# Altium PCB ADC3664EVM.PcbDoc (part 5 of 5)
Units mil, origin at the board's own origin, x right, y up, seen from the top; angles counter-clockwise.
Board outline 3900 x 2716.54 mil, 10 copper layers (Top Layer, L2 GND, L3 PWR, L4 GND, L5 SIG, L6 GND, L7 GND, L8 PWR, L9 GND, Bottom Layer), stack 61.2 mil thick; 332 components, 223 nets, 1425 pads, 969 vias.
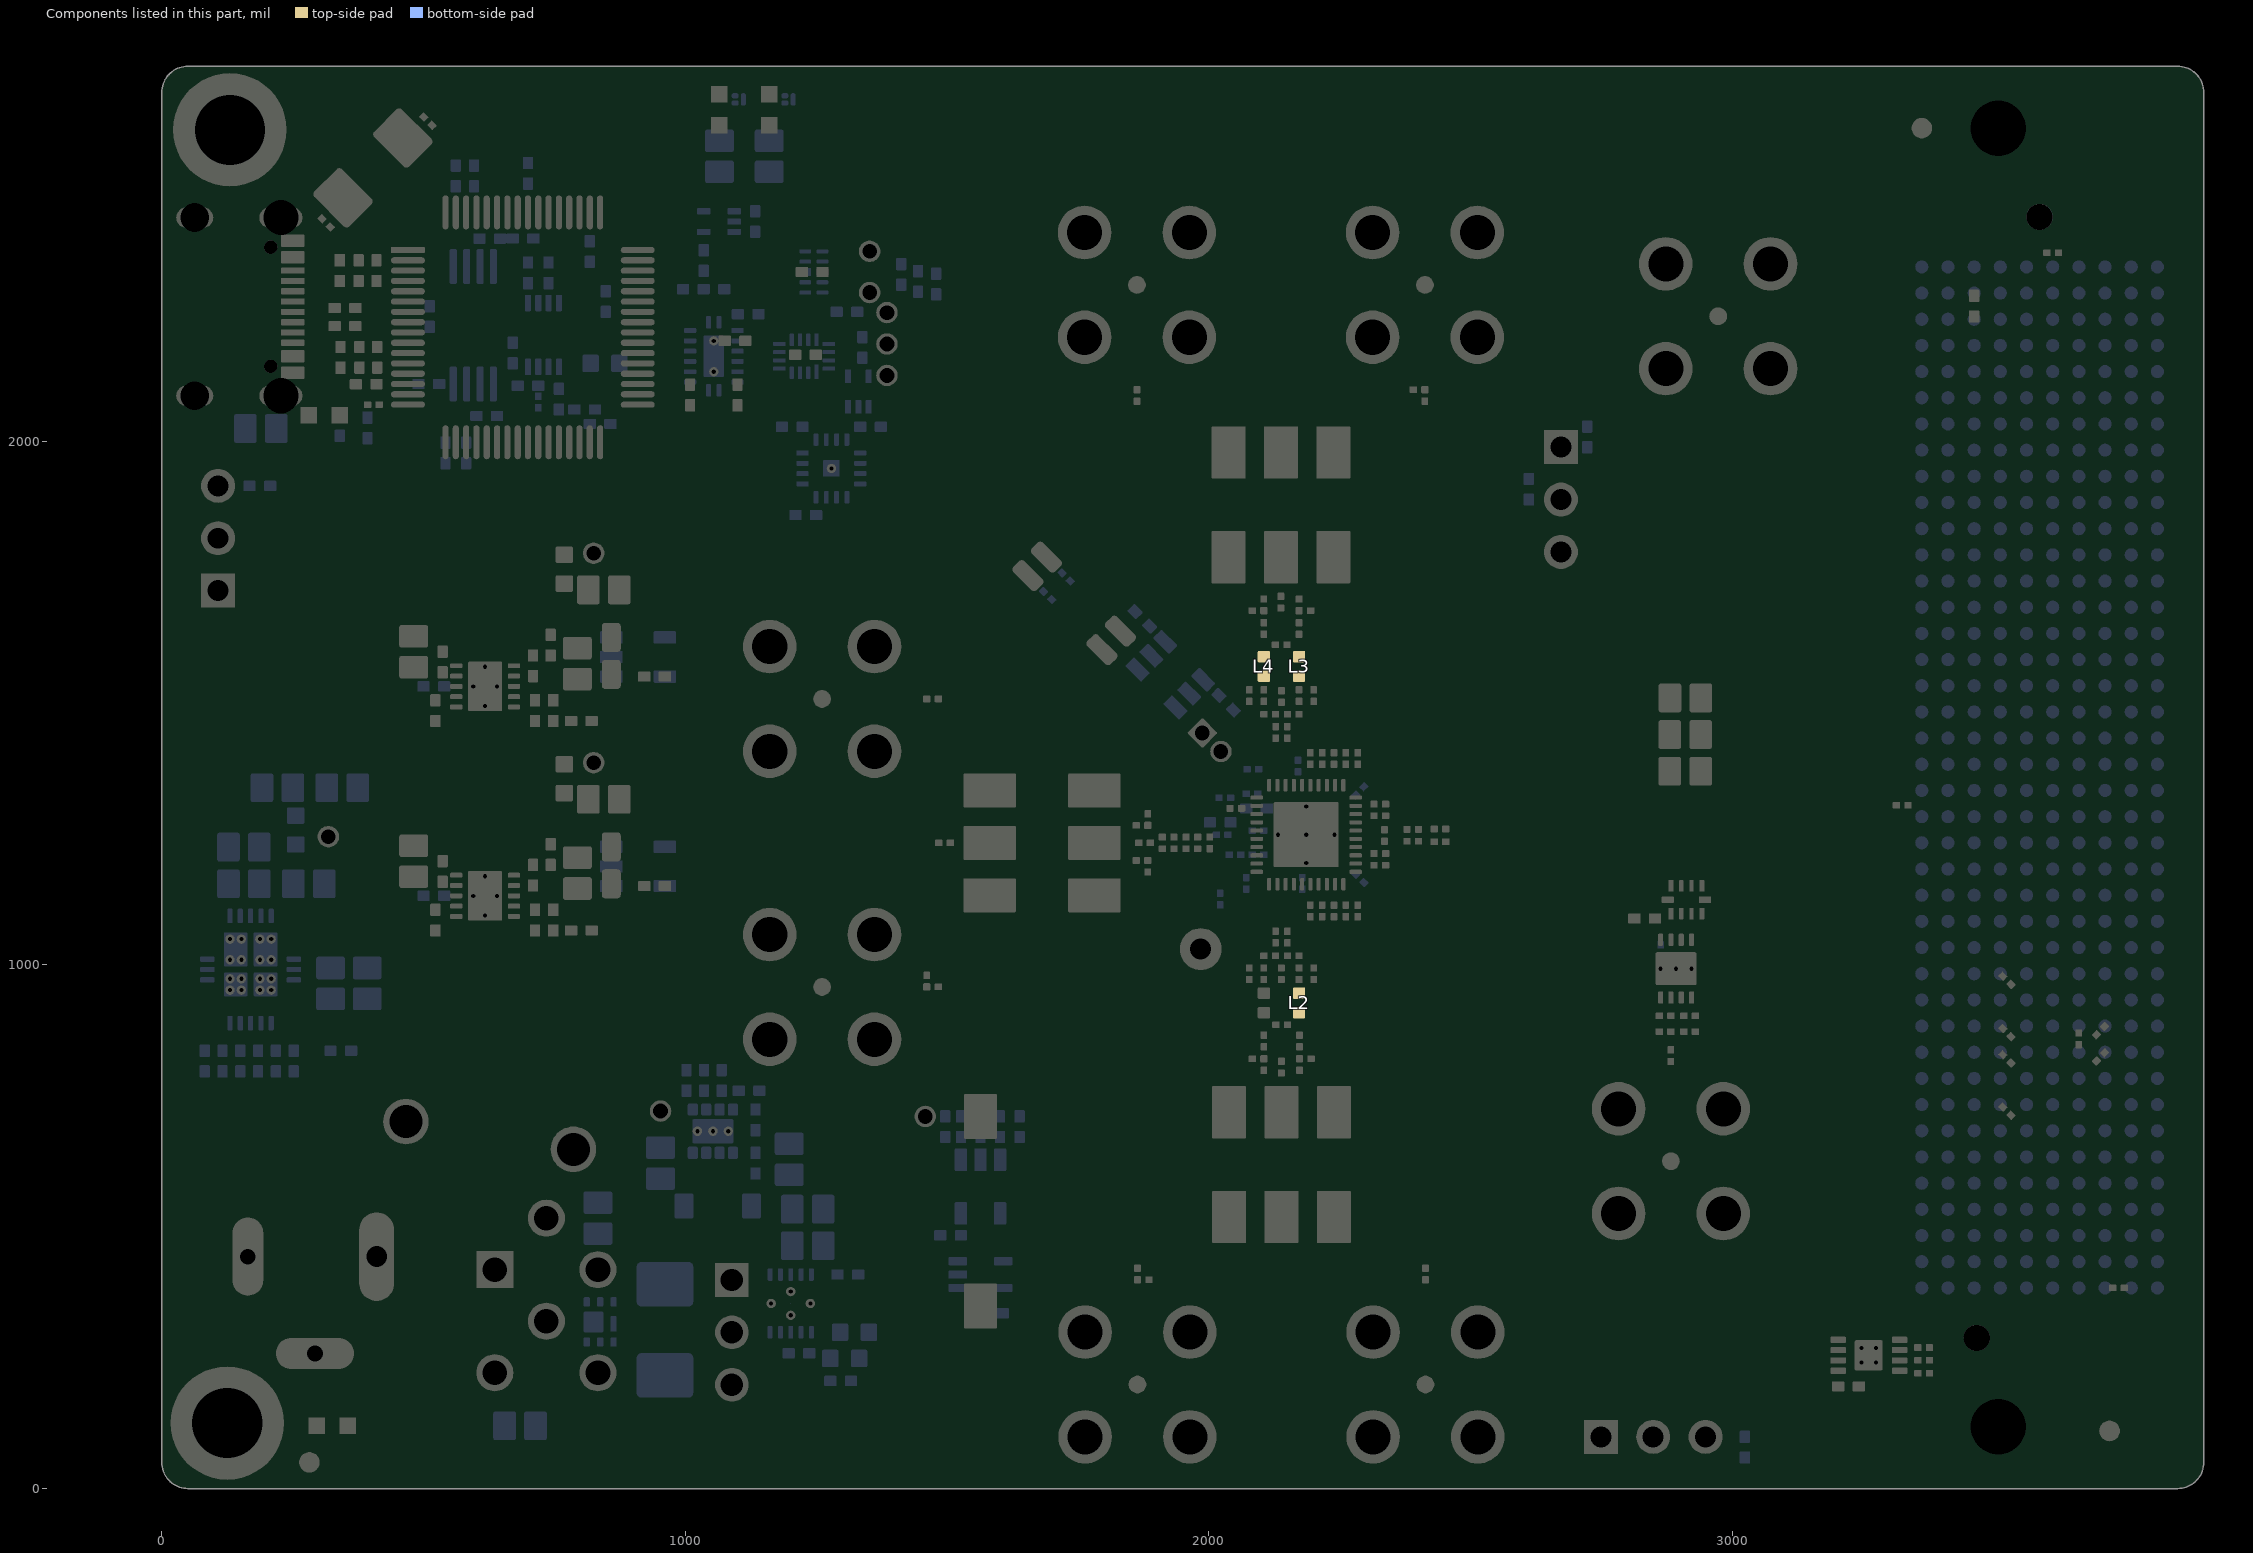
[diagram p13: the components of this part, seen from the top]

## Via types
v1: diameter 18, hole 8, Top Layer to Bottom Layer, tented both sides, 952 vias
v2: diameter 40, hole 20, Top Layer to Bottom Layer, tented both sides, 14 vias
v3: diameter 18, hole 8, Top Layer to Bottom Layer, tented bottom, 3 vias

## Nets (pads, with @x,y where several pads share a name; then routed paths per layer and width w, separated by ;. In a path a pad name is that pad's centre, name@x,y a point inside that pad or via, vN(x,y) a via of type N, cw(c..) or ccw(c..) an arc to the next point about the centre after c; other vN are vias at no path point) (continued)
pads on no net: FID1.1 FID2.1 FID3.1 H1. H3. J1. J1.A2 J1.A3 J1.A6 J1.A7 J1.A10 J1.A11 J1.A14 J1.A15 J1.A18 J1.A19 J1.A22 J1.A23 J1.A26 J1.A27 J1.A30 J1.A31 J1.A34 J1.A35 J1.A38 J1.A39 J1.B1 J1.B4 J1.B5 J1.B8 J1.B9 J1.B12 J1.B13 J1.B16 J1.B17 J1.B20 J1.B21 J1.B24 J1.B25 J1.B28 J1.B29 J1.B32 J1.B33 J1.B36 J1.B37 J1.C2 J1.C3 J1.C6 J1.C7 J1.C10 J1.C11 J1.C14 J1.C15 J1.C18 J1.C19 J1.C22 J1.C23 J1.C26 J1.C27 J1.C39 J1.D4 J1.D5 J1.D14 J1.D15 J1.D17 J1.D18 J1.D20 J1.D21 J1.D23 J1.D24 J1.D26 J1.D27 J1.D29 J1.D33 J1.D34 J1.D36 J1.D38 J1.D40 J1.E2 J1.E3 J1.E6 J1.E7 J1.E9 J1.E10 J1.E12 J1.E13 J1.E15 J1.E16 J1.E18 J1.E19 J1.E21 J1.E22 J1.E24 J1.E25 J1.E27 J1.E28 J1.E30 J1.E31 J1.E33 J1.E34 J1.E36 J1.E37 J1.F4 J1.F5 J1.F7 J1.F8 J1.F10 J1.F11 J1.F13 J1.F14 J1.F16 J1.F17 J1.F19 J1.F20 J1.F22 J1.F23 J1.F25 J1.F26 J1.F28 J1.F29 J1.F31 J1.F32 J1.F34 J1.F35 J1.F37 J1.F38 J1.G2 J1.G3 J1.G12 J1.G13 J1.G15 J1.G16 J1.G18 J1.G19 J1.G22 J1.G24 J1.G25 J1.G27 J1.G34 J1.G36 J1.G37 J1.H1 J1.H10 J1.H11 J1.H16 J1.H17 J1.H19 J1.H20 J1.H22 J1.H23 J1.H25 J1.H26 J1.H28 J1.H29 J1.H31 J1.H32 J1.H34 J1.H35 J1.H37 J1.H38 J1.J2 J1.J3 J1.J6 J1.J7 J1.J9 J1.J10 J1.J12 J1.J13 J1.J15 J1.J16 J1.J18 J1.J19 J1.J21 J1.J22 J1.J24 J1.J25 J1.J27 J1.J28 J1.J30 J1.J31 J1.J33 J1.J34 J1.J36 J1.J37 J1.J39 J1.K1 J1.K4 J1.K5 J1.K7 J1.K8 J1.K10 J1.K11 J1.K13 J1.K14 J1.K16 J1.K17 J1.K19 J1.K20 J1.K22 J1.K23 J1.K25 J1.K27 J1.K28 J1.K29 J1.K31 J1.K32 J1.K34 J1.K35 J1.K37 J1.K38 J1.K40 J3. J3.A5 J3.A8 J3.B5 J3.B8 Q1.0 Q2.1@1095,2645.24 Q2.2@1095,2660.98 Q3.1@1190,2645.24 Q3.2@1190,2660.98 R100.1 R100.2 R101.1 R101.2 R102.1 R102.2 SH-J1.0 U2.9 U3.0 U4.4 U11.21 U11.22 U11.23 U11.24 U11.29 U11.30 U11.32 U11.33 U11.34 U11.36 U11.38 U11.39 U11.40 U11.41 U11.43 U11.44 U11.45 U11.46 U11.48 U11.52 U11.53 U11.54 U11.55 U11.57 U11.58 U11.59 U11.60 U12.6 U12.7 U13.3@1228.98,2323.6 U13.8@1261.85,2323.6 U15.10 U15.11 U15.12 U18.5 U21.5

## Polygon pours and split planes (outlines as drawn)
GND on L8 PWR "L2 GND-GND" (solid, remove dead copper, pour order 102): 3900,-3.61 3900,2716.53 0,2716.54 0,-3.61
3p3V_Utility on L8 PWR "L8 PWR-3p3V_Utility" (solid, remove dead copper, pour order 97): 155,760 265,760 265,1015 595,1015 595,605.64 1290,605.64 1290,416.86 786.24,416.86 786.24,-5 3320,-5 3320,100 1035,100 1035,248.29 3017.11,248.29 3017.11,2015 1389.6,2015 1389.6,2545 1390,2545 1390,2716.54 1265,2716.54 1265,2622.3 155,2622.3
2p3V on L8 PWR "vcm" (solid, remove dead copper, pour order 48): 170,1140 560,1140 560,1422.72 496.81,1422.72 496.81,1505.28 570,1505.28 570,1705 170,1705
12V on L8 PWR "L8 PWR-12V" (solid, remove dead copper, pour order 34): 0,-5 275,-5 275.6,-5 790,-5 790,416.86 1290,416.86 1290,605.64 595,605.64 595,1015 275.6,1015 275.6,745 140,745 140,2635 1257.39,2635 1257.39,2715 0,2715
1p8V_LVLSHIFT on L8 PWR "1" (solid, pour order 24): 1580,1639.12 1755,1639.12 1755,2415 1405,2415 1405,1640 1580,1640
12V_FMC on L8 PWR "gnd" (solid, remove dead copper, pour order 69): 3635,660 3791.17,660 3791.17,105 997.3,105 997.3,253.29 2785,253.29 3635,253.29
VCORE on L8 PWR "L10 PWR-VCORE" (solid, remove dead copper, pour order 55): 948.98,2112.51 948.98,2470 637.92,2470 637.92,2479.2 470,2479.2 470,2126.19 637.92,2126.19 637.92,2410 876.5,2410 876.5,2192.06 845,2192.06 845,2112.51
GND on L5 SIG "L2 GND-GND" (solid, remove dead copper, pour order 101): 3900,-3.61 3900,2716.53 0,2716.54 0,-3.61
GND on L5 SIG "gnd" (solid, remove dead copper, pour order 54): 1895,1450 1895,1235 2130,1235 2130,1450
VREF on L5 SIG "gnd" (solid, remove dead copper, pour order 39): 1978.88,1424.46 1978.88,1285 2085.6,1285 2085.6,1424.46
VCM on L5 SIG "L5 SIG-VCM" (solid, remove dead copper, pour order 42): 1885,945 2468.65,945 2468.65,1540 2080,1540 2080,1480.69 2130,1480.69 2130,1225 1885,1225
EXTGND on L5 SIG "NONET_L-01_P-001" (solid, remove dead copper, pour order 38): 688.31,766.34 0,766.34 0,50 ccw(c50,50) 50,0 688.31,0
GND on L2 GND "L2 GND-GND" (solid, remove dead copper, pour order 71): 3900,-3.61 3900,2716.53 0,2716.54 0,-3.61
EXTGND on L2 GND "NONET_L-01_P-001" (solid, remove dead copper, pour order 7): 688.31,766.34 0,766.34 0,50 ccw(c50,50) 50,0 688.31,0
GND on L6 GND "L2 GND-GND" (solid, remove dead copper, pour order 76): 3900,-3.61 3900,2716.53 556.54,2716.54 ccw(c556.53,2660.06) 536.65,2712.92 56.54,2712.92 ccw(c56.53,2656.39) 0,2656.39 0,46.39 ccw(c50,46.39) 50,-3.61
EXTGND on L6 GND "NONET_L-01_P-001" (solid, remove dead copper, pour order 57): 688.31,766.34 0,766.34 0,50 ccw(c50,50) 50,0 688.31,0
GND on Top Layer "L2 GND-GND" (solid, remove dead copper, pour order 99): 3900,-3.61 3900,2716.53 0,2716.54 0,-3.61
EXTGND on Top Layer "NONET_L-01_P-001" (solid, remove dead copper, pour order 58): 688.31,766.34 0,766.34 0,50 ccw(c50,50) 50,0 688.31,0
GND on L4 GND "L2 GND-GND" (solid, remove dead copper, pour order 74): 3900,-3.61 3900,2716.53 556.54,2716.54 ccw(c556.53,2660.06) 536.65,2712.92 56.54,2712.92 ccw(c56.53,2656.39) 0,2656.39 0,46.39 ccw(c50,46.39) 50,-3.61
EXTGND on L4 GND "NONET_L-01_P-001" (solid, remove dead copper, pour order 59): 688.31,766.34 0,766.34 0,50 ccw(c50,50) 50,0 688.31,0
GND on L7 GND "L2 GND-GND" (solid, remove dead copper, pour order 77): 3900,-3.61 3900,2716.53 556.54,2716.54 ccw(c556.53,2660.06) 536.65,2712.92 56.54,2712.92 ccw(c56.53,2656.39) 0,2656.39 0,46.39 ccw(c50,46.39) 50,-3.61
EXTGND on L7 GND "NONET_L-01_P-001" (solid, remove dead copper, pour order 60): 688.31,766.34 0,766.34 0,50 ccw(c50,50) 50,0 688.31,0
GND on L9 GND "L2 GND-GND" (solid, remove dead copper, pour order 78): 3900,-3.61 3900,2716.53 556.54,2716.54 ccw(c556.53,2660.06) 536.65,2712.92 56.54,2712.92 ccw(c56.53,2656.39) 0,2656.39 0,46.39 ccw(c50,46.39) 50,-3.61
EXTGND on L9 GND "NONET_L-01_P-001" (solid, remove dead copper, pour order 61): 688.31,766.34 0,766.34 0,50 ccw(c50,50) 50,0 688.31,0
GND on L3 PWR "L2 GND-GND" (solid, remove dead copper, pour order 96): 3900,-3.61 3900,2716.53 556.54,2716.54 ccw(c556.53,2660.06) 536.65,2712.92 56.54,2712.92 ccw(c56.53,2656.39) 0,2656.39 0,46.39 ccw(c50,46.39) 50,-3.61
1p8V_LVLSHIFT on L3 PWR "L3 PWR-1p8V_LVLSHIFT" (solid, pour order 90): 2636.58,697.88 3106.62,697.88 3106.62,2712.92 0,2712.92 0,887.5 1224.31,887.5 1224.31,0 1659.39,0 1659.39,1188.15 1366.99,1188.15 709.12,1191.1 269.17,1191.1 269.17,2033.32 2636.58,2033.32
1p8V_AVDD on L3 PWR "L3 PWR-1p8V_AVDD" (solid, remove dead copper, pour order 92): 2018.18,936.33 2018.64,879.73 2333.72,879.73 2333.72,936.33 2198.25,936.33 2198.25,1785 385,1785 385,1435 2018.64,1435 2018.64,936.33
3p3V_AUX on L3 PWR "vcm" (solid, remove dead copper, pour order 93): 3270,340 3270,0 3900,0 3900,820 3575,820 3575,340
3p3V_EEPROM on L3 PWR "vcm" (solid, remove dead copper, pour order 94): 3270,340 2875,340 2875,0 3270,0 3270,100
1p8V_IOVDD on L3 PWR "L3_PWR_1P8V_IOVDD_P095" (solid, remove dead copper, pour order 95): 385,1205.06 1741.07,1205.06 1741.07,376.16 2621.28,376.16 2621.28,1419.71 2263.63,1419.71 2263.63,819.66 1994.38,819.66 1994.38,1381.33 385,1381.33
EXTGND on L3 PWR "NONET_L-01_P-001" (solid, remove dead copper, pour order 91): 688.31,766.34 0,766.34 0,50 ccw(c50,50) 50,0 688.31,0
GND on Bottom Layer "L2 GND-GND" (solid, remove dead copper, pour order 103): 3900,-3.61 3900,2716.53 0,2716.54 0,-3.61

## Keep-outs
Keep-Out Layer:
  text ".Layer_Name" at 577,-858.49 h60

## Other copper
Top Layer:
  drawing of 99 lines, arcs and shapes, not listed
  text ".Layer_Name" at 577,-858.49 h60
L2 GND:
  pour cut-out: 2907.99,625.2 ccw(c2882.27,625.27) 2900.45,643.45 ccw(c2882.93,625.93) 2882.93,650.72 2881.55,650.72 ccw(c2881.55,625.98) 2864.06,643.47 2863.35,642.76 ccw(c2880.85,625.27) 2856.11,625.27 2856.11,624.57 ccw(c2881.56,624.57) 2863.56,606.57 2863.7,606.43 ccw(c2882.05,624.77) 2882.05,598.83 ccw(c2882.05,624.75) 2900.38,606.42 2900.75,606.79 ccw(c2883.27,624.27) 2907.99,624.27
  pour cut-out: 2998.18,2238.8 ccw(c2972.46,2238.88) 2990.65,2257.06 ccw(c2973.12,2239.54) 2973.12,2264.32 2971.75,2264.32 ccw(c2971.75,2239.59) 2954.26,2257.08 2953.55,2256.37 ccw(c2971.04,2238.88) 2946.3,2238.88 2946.3,2238.17 ccw(c2971.76,2238.17) 2953.76,2220.17 2953.9,2220.03 ccw(c2972.24,2238.38) 2972.24,2212.44 ccw(c2972.24,2238.36) 2990.58,2220.03 2990.94,2220.4 ccw(c2973.47,2237.87) 2998.18,2237.87
  pour cut-out: 2438.18,2298.8 ccw(c2412.46,2298.88) 2430.65,2317.06 ccw(c2413.12,2299.54) 2413.12,2324.32 2411.75,2324.32 ccw(c2411.75,2299.59) 2394.26,2317.08 2393.55,2316.37 ccw(c2411.04,2298.88) 2386.3,2298.88 2386.3,2298.17 ccw(c2411.76,2298.17) 2393.76,2280.17 2393.9,2280.03 ccw(c2412.24,2298.38) 2412.24,2272.44 ccw(c2412.24,2298.36) 2430.58,2280.03 2430.94,2280.4 ccw(c2413.47,2297.87) 2438.18,2297.87
  pour cut-out: 1888.18,2298.8 ccw(c1862.46,2298.88) 1880.65,2317.06 ccw(c1863.12,2299.54) 1863.12,2324.32 1861.75,2324.32 ccw(c1861.75,2299.59) 1844.26,2317.08 1843.55,2316.37 ccw(c1861.04,2298.88) 1836.3,2298.88 1836.3,2298.17 ccw(c1861.76,2298.17) 1843.76,2280.17 1843.9,2280.03 ccw(c1862.24,2298.38) 1862.24,2272.44 ccw(c1862.24,2298.36) 1880.58,2280.03 1880.94,2280.4 ccw(c1863.47,2297.87) 1888.18,2297.87
  pour cut-out: 2387.73,198.79 ccw(c2413.44,198.72) 2395.26,180.53 ccw(c2412.79,198.06) 2412.79,173.27 2414.16,173.27 ccw(c2414.16,198) 2431.65,180.52 2432.36,181.23 ccw(c2414.86,198.72) 2439.61,198.72 2439.61,199.42 ccw(c2414.15,199.42) 2432.15,217.42 2432.01,217.56 ccw(c2413.67,199.22) 2413.67,225.16 ccw(c2413.67,199.23) 2395.33,217.57 2394.97,217.2 ccw(c2412.44,199.72) 2387.73,199.72
  pour cut-out: 1837.73,198.79 ccw(c1863.44,198.72) 1845.26,180.53 ccw(c1862.79,198.06) 1862.79,173.27 1864.16,173.27 ccw(c1864.16,198) 1881.65,180.52 1882.36,181.23 ccw(c1864.86,198.72) 1889.61,198.72 1889.61,199.42 ccw(c1864.15,199.42) 1882.15,217.42 1882.01,217.56 ccw(c1863.67,199.22) 1863.67,225.16 ccw(c1863.67,199.23) 1845.33,217.57 1844.97,217.2 ccw(c1862.44,199.72) 1837.73,199.72
  pour cut-out: 1261.18,983.77 ccw(c1261.11,958.05) 1242.92,976.24 ccw(c1260.45,958.71) 1235.66,958.71 1235.66,957.33 ccw(c1260.39,957.33) 1242.9,939.85 1243.61,939.14 ccw(c1261.11,956.63) 1261.11,931.89 1261.81,931.89 ccw(c1261.81,957.35) 1279.81,939.35 1279.95,939.49 ccw(c1261.61,957.83) 1287.55,957.83 ccw(c1261.62,957.83) 1279.95,976.16 1279.59,976.53 ccw(c1262.11,959.05) 1262.11,983.77
  pour cut-out: 1261.18,1533.77 ccw(c1261.11,1508.05) 1242.92,1526.24 ccw(c1260.45,1508.71) 1235.66,1508.71 1235.66,1507.33 ccw(c1260.39,1507.33) 1242.9,1489.85 1243.61,1489.14 ccw(c1261.11,1506.63) 1261.11,1481.89 1261.81,1481.89 ccw(c1261.81,1507.35) 1279.81,1489.35 1279.95,1489.49 ccw(c1261.61,1507.83) 1287.55,1507.83 ccw(c1261.62,1507.83) 1279.95,1526.16 1279.59,1526.53 ccw(c1262.11,1509.05) 1262.11,1533.77
  pour cut-out: 2074.96,1833.88 2074.96,1723.88 1999.96,1723.88 1999.96,1833.88
  pour cut-out: 2274.96,1833.88 2274.96,1723.88 2199.96,1723.88 2199.96,1833.88
  pour cut-out: 2274.96,2033.88 2274.96,1923.88 2199.96,1923.88 2199.96,2033.88
  pour cut-out: 2200.95,663.72 2200.95,773.72 2275.95,773.72 2275.95,663.72
  pour cut-out: 2000.95,663.72 2000.95,773.72 2075.95,773.72 2075.95,663.72
  pour cut-out: 2000.95,463.72 2000.95,573.72 2075.95,573.72 2075.95,463.72
  pour cut-out: 1726.11,1295.55 1836.11,1295.55 1836.11,1370.55 1726.11,1370.55
  pour cut-out: 1726.11,1095.55 1836.11,1095.55 1836.11,1170.55 1726.11,1170.55
  pour cut-out: 1526.11,1095.55 1636.11,1095.55 1636.11,1170.55 1526.11,1170.55
  text ".Layer_Name" at 575,-860 h60
L3 PWR:
  pour cut-out: 2239.63,1237.8 cw(c2239.63,1248.8) 2228.63,1248.8 cw(c2239.63,1248.8) 2239.63,1259.8 cw(c2239.63,1248.8) 2250.63,1248.8 cw(c2239.63,1248.8)
  pour cut-out: 2907.99,625.2 ccw(c2882.27,625.27) 2900.45,643.45 ccw(c2882.93,625.93) 2882.93,650.72 2881.55,650.72 ccw(c2881.55,625.98) 2864.06,643.47 2863.35,642.76 ccw(c2880.85,625.27) 2856.11,625.27 2856.11,624.57 ccw(c2881.56,624.57) 2863.56,606.57 2863.7,606.43 ccw(c2882.05,624.77) 2882.05,598.83 ccw(c2882.05,624.75) 2900.38,606.42 2900.75,606.79 ccw(c2883.27,624.27) 2907.99,624.27
  pour cut-out: 2998.18,2238.8 ccw(c2972.46,2238.88) 2990.65,2257.06 ccw(c2973.12,2239.54) 2973.12,2264.32 2971.75,2264.32 ccw(c2971.75,2239.59) 2954.26,2257.08 2953.55,2256.37 ccw(c2971.04,2238.88) 2946.3,2238.88 2946.3,2238.17 ccw(c2971.76,2238.17) 2953.76,2220.17 2953.9,2220.03 ccw(c2972.24,2238.38) 2972.24,2212.44 ccw(c2972.24,2238.36) 2990.58,2220.03 2990.94,2220.4 ccw(c2973.47,2237.87) 2998.18,2237.87
  pour cut-out: 2261.36,1436.62 cw(c2261.36,1447.62) 2250.36,1447.62 cw(c2261.36,1447.62) 2261.36,1458.62 cw(c2261.36,1447.62) 2272.36,1447.62 cw(c2261.36,1447.62)
  pour cut-out: 2216.16,1436.62 cw(c2216.16,1447.62) 2205.16,1447.62 cw(c2216.16,1447.62) 2216.16,1458.62 cw(c2216.16,1447.62) 2227.16,1447.62 cw(c2216.16,1447.62)
  pour cut-out: 2180.47,1425.31 cw(c2180.47,1436.31) 2169.47,1436.31 cw(c2180.47,1436.31) 2180.47,1447.31 cw(c2180.47,1436.31) 2191.47,1436.31 cw(c2180.47,1436.31)
  pour cut-out: 2198.41,1445.49 cw(c2198.41,1456.49) 2187.41,1456.49 cw(c2198.41,1456.49) 2198.41,1467.49 cw(c2198.41,1456.49) 2209.41,1456.49 cw(c2198.41,1456.49)
  pour cut-out: 2207.91,1597.91 cw(c2207.91,1608.91) 2196.91,1608.91 cw(c2207.91,1608.91) 2207.91,1619.91 cw(c2207.91,1608.91) 2218.91,1608.91 cw(c2207.91,1608.91)
  pour cut-out: 2202.84,1641 cw(c2202.84,1652) 2191.84,1652 cw(c2202.84,1652) 2202.84,1663 cw(c2202.84,1652) 2213.84,1652 cw(c2202.84,1652)
  pour cut-out: 1862.46,2330.88 cw(c1862.46,2341.88) 1851.46,2341.88 cw(c1862.46,2341.88) 1862.46,2352.88 cw(c1862.46,2341.88) 1873.46,2341.88 cw(c1862.46,2341.88)
  pour cut-out: 2412.46,2330.88 cw(c2412.46,2341.88) 2401.46,2341.88 cw(c2412.46,2341.88) 2412.46,2352.88 cw(c2412.46,2341.88) 2423.46,2341.88 cw(c2412.46,2341.88)
  pour cut-out: 2442.87,2318.28 cw(c2442.87,2329.28) 2431.87,2329.28 cw(c2442.87,2329.28) 2442.87,2340.28 cw(c2442.87,2329.28) 2453.87,2329.28 cw(c2442.87,2329.28)
  pour cut-out: 2382.06,2318.28 cw(c2382.06,2329.28) 2371.06,2329.28 cw(c2382.06,2329.28) 2382.06,2340.28 cw(c2382.06,2329.28) 2393.06,2329.28 cw(c2382.06,2329.28)
  pour cut-out: 1892.87,2318.28 cw(c1892.87,2329.28) 1881.87,2329.28 cw(c1892.87,2329.28) 1892.87,2340.28 cw(c1892.87,2329.28) 1903.87,2329.28 cw(c1892.87,2329.28)
  pour cut-out: 1832.06,2318.28 cw(c1832.06,2329.28) 1821.06,2329.28 cw(c1832.06,2329.28) 1832.06,2340.28 cw(c1832.06,2329.28) 1843.06,2329.28 cw(c1832.06,2329.28)
  pour cut-out: 921.46,1139.75 cw(c921.46,1150.75) 910.46,1150.75 cw(c921.46,1150.75) 921.46,1161.75 cw(c921.46,1150.75) 932.46,1150.75 cw(c921.46,1150.75)
  pour cut-out: 3761.42,822.27 cw(c3761.42,833.27) 3750.42,833.27 cw(c3761.42,833.27) 3761.42,844.27 cw(c3761.42,833.27) 3772.42,833.27 cw(c3761.42,833.27)
  pour cut-out: 3561.42,722.27 cw(c3561.42,733.27) 3550.42,733.27 cw(c3561.42,733.27) 3561.42,744.27 cw(c3561.42,733.27) 3572.42,733.27 cw(c3561.42,733.27)
  pour cut-out: 3560.12,570.57 cw(c3560.12,581.57) 3549.12,581.57 cw(c3560.12,581.57) 3560.12,592.57 cw(c3560.12,581.57) 3571.12,581.57 cw(c3560.12,581.57)
  pour cut-out: 3561.42,422.27 cw(c3561.42,433.27) 3550.42,433.27 cw(c3561.42,433.27) 3561.42,444.27 cw(c3561.42,433.27) 3572.42,433.27 cw(c3561.42,433.27)
  pour cut-out: 2383.73,356.91 cw(c2383.73,367.91) 2372.73,367.91 cw(c2383.73,367.91) 2383.73,378.91 cw(c2383.73,367.91) 2394.73,367.91 cw(c2383.73,367.91)
  pour cut-out: 2443.17,362.52 cw(c2443.17,373.52) 2432.17,373.52 cw(c2443.17,373.52) 2443.17,384.52 cw(c2443.17,373.52) 2454.17,373.52 cw(c2443.17,373.52)
  pour cut-out: 1978.88,358 cw(c1978.88,369) 1967.88,369 cw(c1978.88,369) 1978.88,380 cw(c1978.88,369) 1989.88,369 cw(c1978.88,369)
  pour cut-out: 1920.88,358 cw(c1920.88,369) 1909.88,369 cw(c1920.88,369) 1920.88,380 cw(c1920.88,369) 1931.88,369 cw(c1920.88,369)
  pour cut-out: 1893.17,362.52 cw(c1893.17,373.52) 1882.17,373.52 cw(c1893.17,373.52) 1893.17,384.52 cw(c1893.17,373.52) 1904.17,373.52 cw(c1893.17,373.52)
  pour cut-out: 1833.73,356.91 cw(c1833.73,367.91) 1822.73,367.91 cw(c1833.73,367.91) 1833.73,378.91 cw(c1833.73,367.91) 1844.73,367.91 cw(c1833.73,367.91)
  pour cut-out: 1824.06,1413.46 cw(c1824.06,1424.46) 1813.06,1424.46 cw(c1824.06,1424.46) 1824.06,1435.46 cw(c1824.06,1424.46) 1835.06,1424.46 cw(c1824.06,1424.46)
  pour cut-out: 2063.68,1013.29 cw(c2063.68,1024.29) 2052.68,1024.29 cw(c2063.68,1024.29) 2063.68,1035.29 cw(c2063.68,1024.29) 2074.68,1024.29 cw(c2063.68,1024.29)
  pour cut-out: 2260.18,1245.67 cw(c2260.18,1256.67) 2249.18,1256.67 cw(c2260.18,1256.67) 2260.18,1267.67 cw(c2260.18,1256.67) 2271.18,1256.67 cw(c2260.18,1256.67)
  pour cut-out: 2244.75,1214.18 cw(c2244.75,1225.18) 2233.75,1225.18 cw(c2244.75,1225.18) 2244.75,1236.18 cw(c2244.75,1225.18) 2255.75,1225.18 cw(c2244.75,1225.18)
  pour cut-out: 1980.33,1776.9 cw(c1980.33,1787.9) 1969.33,1787.9 cw(c1980.33,1787.9) 1980.33,1798.9 cw(c1980.33,1787.9) 1991.33,1787.9 cw(c1980.33,1787.9)
  pour cut-out: 1836.08,1780.35 cw(c1836.08,1791.35) 1825.08,1791.35 cw(c1836.08,1791.35) 1836.08,1802.35 cw(c1836.08,1791.35) 1847.08,1791.35 cw(c1836.08,1791.35)
  pour cut-out: 1888.18,2298.8 ccw(c1862.46,2298.88) 1880.65,2317.06 ccw(c1863.12,2299.54) 1863.12,2324.32 1861.75,2324.32 ccw(c1861.75,2299.59) 1844.26,2317.08 1843.55,2316.37 ccw(c1861.04,2298.88) 1836.3,2298.88 1836.3,2298.17 ccw(c1861.76,2298.17) 1843.76,2280.17 1843.9,2280.03 ccw(c1862.24,2298.38) 1862.24,2272.44 ccw(c1862.24,2298.36) 1880.58,2280.03 1880.94,2280.4 ccw(c1863.47,2297.87) 1888.18,2297.87
  pour cut-out: 2438.18,2298.8 ccw(c2412.46,2298.88) 2430.65,2317.06 ccw(c2413.12,2299.54) 2413.12,2324.32 2411.75,2324.32 ccw(c2411.75,2299.59) 2394.26,2317.08 2393.55,2316.37 ccw(c2411.04,2298.88) 2386.3,2298.88 2386.3,2298.17 ccw(c2411.76,2298.17) 2393.76,2280.17 2393.9,2280.03 ccw(c2412.24,2298.38) 2412.24,2272.44 ccw(c2412.24,2298.36) 2430.58,2280.03 2430.94,2280.4 ccw(c2413.47,2297.87) 2438.18,2297.87
  pour cut-out: 2387.73,198.79 ccw(c2413.44,198.72) 2395.26,180.53 ccw(c2412.79,198.06) 2412.79,173.27 2414.16,173.27 ccw(c2414.16,198) 2431.65,180.52 2432.36,181.23 ccw(c2414.86,198.72) 2439.61,198.72 2439.61,199.42 ccw(c2414.15,199.42) 2432.15,217.42 2432.01,217.56 ccw(c2413.67,199.22) 2413.67,225.16 ccw(c2413.67,199.23) 2395.33,217.57 2394.97,217.2 ccw(c2412.44,199.72) 2387.73,199.72
  pour cut-out: 1837.73,198.79 ccw(c1863.44,198.72) 1845.26,180.53 ccw(c1862.79,198.06) 1862.79,173.27 1864.16,173.27 ccw(c1864.16,198) 1881.65,180.52 1882.36,181.23 ccw(c1864.86,198.72) 1889.61,198.72 1889.61,199.42 ccw(c1864.15,199.42) 1882.15,217.42 1882.01,217.56 ccw(c1863.67,199.22) 1863.67,225.16 ccw(c1863.67,199.23) 1845.33,217.57 1844.97,217.2 ccw(c1862.44,199.72) 1837.73,199.72
  pour cut-out: 1261.18,983.77 ccw(c1261.11,958.05) 1242.92,976.24 ccw(c1260.45,958.71) 1235.66,958.71 1235.66,957.33 ccw(c1260.39,957.33) 1242.9,939.85 1243.61,939.14 ccw(c1261.11,956.63) 1261.11,931.89 1261.81,931.89 ccw(c1261.81,957.35) 1279.81,939.35 1279.95,939.49 ccw(c1261.61,957.83) 1287.55,957.83 ccw(c1261.62,957.83) 1279.95,976.16 1279.59,976.53 ccw(c1262.11,959.05) 1262.11,983.77
  pour cut-out: 1261.18,1533.77 ccw(c1261.11,1508.05) 1242.92,1526.24 ccw(c1260.45,1508.71) 1235.66,1508.71 1235.66,1507.33 ccw(c1260.39,1507.33) 1242.9,1489.85 1243.61,1489.14 ccw(c1261.11,1506.63) 1261.11,1481.89 1261.81,1481.89 ccw(c1261.81,1507.35) 1279.81,1489.35 1279.95,1489.49 ccw(c1261.61,1507.83) 1287.55,1507.83 ccw(c1261.62,1507.83) 1279.95,1526.16 1279.59,1526.53 ccw(c1262.11,1509.05) 1262.11,1533.77
  pour cut-out: 2074.96,1833.88 2074.96,1723.88 1999.96,1723.88 1999.96,1833.88
  pour cut-out: 2274.96,1833.88 2274.96,1723.88 2199.96,1723.88 2199.96,1833.88
  pour cut-out: 2274.96,2033.88 2274.96,1923.88 2199.96,1923.88 2199.96,2033.88
  pour cut-out: 2200.95,663.72 2200.95,773.72 2275.95,773.72 2275.95,663.72
  pour cut-out: 2000.95,663.72 2000.95,773.72 2075.95,773.72 2075.95,663.72
  pour cut-out: 2000.95,463.72 2000.95,573.72 2075.95,573.72 2075.95,463.72
  pour cut-out: 1726.11,1295.55 1836.11,1295.55 1836.11,1370.55 1726.11,1370.55
  pour cut-out: 1726.11,1095.55 1836.11,1095.55 1836.11,1170.55 1726.11,1170.55
  pour cut-out: 1526.11,1095.55 1636.11,1095.55 1636.11,1170.55 1526.11,1170.55
  text ".Layer_Name" at 575,-860 h60
L4 GND:
  text ".Layer_Name" at 575,-860 h60
L7 GND:
  text ".Layer_Name" at 575,-860 h60
L8 PWR:
  pour cut-out: 3220.57,234.09 cw(c3220.57,245.09) 3209.57,245.09 cw(c3220.57,245.09) 3220.57,256.09 cw(c3220.57,245.09) 3231.57,245.09 cw(c3220.57,245.09)
  pour cut-out: 3246.08,229.6 cw(c3246.08,240.6) 3235.08,240.6 cw(c3246.08,240.6) 3246.08,251.6 cw(c3246.08,240.6) 3257.08,240.6 cw(c3246.08,240.6)
  pour cut-out: 3381.1,258.36 cw(c3381.1,269.36) 3370.1,269.36 cw(c3381.1,269.36) 3381.1,280.36 cw(c3381.1,269.36) 3392.1,269.36 cw(c3381.1,269.36)
  pour cut-out: 3381.1,233.68 cw(c3381.1,244.68) 3370.1,244.68 cw(c3381.1,244.68) 3381.1,255.68 cw(c3381.1,244.68) 3392.1,244.68 cw(c3381.1,244.68)
  text ".Layer_Name" at 575,-860 h60
L9 GND:
  text ".Layer_Name" at 575,-860 h60
L5 SIG:
  pour cut-out: 2138.45,923.79 cw(c2138.45,934.79) 2127.45,934.79 cw(c2138.45,934.79) 2138.45,945.79 cw(c2138.45,934.79) 2149.45,934.79 cw(c2138.45,934.79)
  pour cut-out: 2229.69,1544.16 cw(c2229.69,1555.16) 2218.69,1555.16 cw(c2229.69,1555.16) 2229.69,1566.16 cw(c2229.69,1555.16) 2240.69,1555.16 cw(c2229.69,1555.16)
  pour cut-out: 2682.7,1835.48 2684.57,1834.85 2686.5,1834.46 2694.41,1831.19 2696.05,1830.09 2697.82,1829.22 2704.6,1824.01 2705.9,1822.53 2707.39,1821.23 2712.59,1814.44 2713.47,1812.67 2714.56,1811.03 2716.37,1806.67 2819.08,1806.67 2821.63,1806.16 2824.85,1805.52 2826.76,1804.73 2826.77,1804.73 2826.78,1804.72 2831.66,1801.46 3304.08,1329.04 3304.41,1328.98 3305.9,1328.98 3309.41,1328.28 3312.59,1326.96 3314.85,1326.02 3317.82,1324.04 3319.91,1321.95 3321.99,1319.87 3323.98,1316.9 3324.64,1315.3 3326.23,1311.46 3326.93,1307.94 3326.93,1305 3326.93,1302.06 3326.23,1298.54 3324.91,1295.36 3323.98,1293.1 3321.99,1290.13 3319.91,1288.05 3317.82,1285.96 3314.85,1283.98 3313.25,1283.32 3309.41,1281.72 3305.9,1281.02 3302.95,1281.02 3300.01,1281.02 3296.5,1281.72 3293.31,1283.04 3291.06,1283.98 3288.08,1285.96 3286,1288.05 3283.92,1290.13 3281.93,1293.1 3281.27,1294.7 3279.67,1298.54 3278.98,1302.06 3278.98,1303.81 2811.71,1771.08 2716.37,1771.08 2714.56,1766.72 2713.47,1765.08 2712.59,1763.31 2707.39,1756.52 2705.9,1755.22 2704.6,1753.74 2697.82,1748.53 2696.05,1747.66 2694.41,1746.56 2686.5,1743.29 2684.57,1742.9 2682.7,1742.27 2674.22,1741.15 2672.25,1741.28 2670.28,1741.15 2661.8,1742.27 2659.93,1742.9 2658,1743.29 2650.1,1746.56 2648.45,1747.66 2646.68,1748.53 2639.9,1753.74 2638.6,1755.22 2637.11,1756.52 2631.91,1763.31 2631.03,1765.08 2629.94,1766.72 2626.67,1774.62 2626.28,1776.56 2625.65,1778.43 2624.53,1786.91 2624.66,1788.88 2624.53,1790.85 2625.65,1799.32 2626.28,1801.19 2626.67,1803.13 2629.94,1811.03 2631.03,1812.67 2631.91,1814.44 2637.11,1821.23 2638.6,1822.53 2639.9,1824.01 2646.68,1829.22 2648.45,1830.09 2650.1,1831.19 2658,1834.46 2659.93,1834.85 2661.8,1835.48 2670.28,1836.6 2672.25,1836.47 2674.22,1836.6
  pour cut-out: 289 vertices and 0 holes, not listed, extent 1474.6,1637.11 2479.44,2122.9
  text ".Layer_Name" at 575,-860 h60
L6 GND:
  text ".Layer_Name" at 575,-860 h60
Bottom Layer:
  drawing of 46 lines, arcs and shapes, not listed
  text ".Layer_Name" at 577,-858.49 h60
Multi-Layer:
  pour cut-out: 1334.01,1842.77 cw(c1334.01,1853.77) 1323.01,1853.77 cw(c1334.01,1853.77) 1334.01,1864.77 cw(c1334.01,1853.77) 1345.01,1853.77 cw(c1334.01,1853.77)
  pour cut-out: 1244.37,1882.18 cw(c1244.37,1893.18) 1233.37,1893.18 cw(c1244.37,1893.18) 1244.37,1904.18 cw(c1244.37,1893.18) 1255.37,1893.18 cw(c1244.37,1893.18)

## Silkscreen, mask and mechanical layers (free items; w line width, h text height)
Top Overlay:
  drawing of 217 lines, arcs and shapes, not listed
  text "POWER / GOOD" at 1239.25,2560 h90
  text "DUT / SPI" at 1641.44,2105 h70 r90
  text "CTRL" at 996.65,1990.25 h60
  text "ADC36xxEVM / RevG" at 3185,1973.17 h60
  text "HIGH" at 996.63,1947.99 h60
  text "LOW" at 1129.13,1947.99 h60
  text "REF" at 1258.3,1948.29 h60
  text "CLK" at 1378.3,1948.29 h60
  text "ON" at 1031.8,1909.29 h30
  text "OFF" at 1156.8,1909.29 h30
  text "EXT" at 1286.8,1909.29 h30
  text "DIFF" at 1396.8,1909.29 h30
  text "ON" at 1031.8,1849.29 h30
  text "ON" at 1156.8,1849.29 h30
  text "INT" at 1286.8,1849.29 h30
  text "DIFF" at 1396.8,1849.29 h30
  text "OFF" at 1031.8,1793.49 h30
  text "ON" at 1156.8,1793.49 h30
  text "INT" at 1286.8,1793.49 h30
  text "SE" at 1396.8,1793.49 h30
  text "DUT OPTION" at 2850,1545 h100
  text "ADC3663" at 2985,1485 h50
  text "ADC3664" at 2985,1415 h50
  text "ADC3683" at 2985,1345 h50
  text ".Layer_Name" at 577,-858.49 h60
Bottom Overlay:
  lines w7: 1419,2264.6 1464,2264.6
  text ".Layer_Name" at 577,-858.49 h60
Top Paste:
  text ".Layer_Name" at 577,-858.49 h60
Bottom Paste:
  text ".Layer_Name" at 577,-858.49 h60
Top Solder:
  text ".Layer_Name" at 577,-858.49 h60
  text ".Layer_Name" at 577,-858.49 h60
Bottom Solder:
  text ".Layer_Name" at 577,-858.49 h60
Drill Guide:
  text ".Layer_Name" at 577,-858.49 h60
M1 Board Outline:
  lines w5: 0,50 ccw(c50,50) 50,0 100,0 3850,0 ccw(c3850,50) 3900,50 3900,100 3900,2616.53 3900,2666.54 ccw(c3850,2666.54) 3850,2716.54 100,2716.54 50,2716.54 ccw(c50,2666.54) 0,2666.54 0,2616.53 0,100 0,50
  text ".Layer_Name" at 577,-858.49 h60
M2 Board Dimensions:
  rectangle: 125,-400 500,-275
  rectangle: 0,-275 125,-150
  lines w7: 0,-275 1000,-275 ; 125,-400 125,-150 ; 250,-400 250,-150 ; 500,-400 500,-150 ; 750,-400 750,-150 ; 0,-400 0,-150 1000,-150 1000,-400 0,-400
  text ".Layer_Name" at 577,-858.49 h60
M3 3D STEP Top:
  text ".Layer_Name" at 577,-858.49 h60
M4 3D STEP Bottom:
  text ".Layer_Name" at 577,-858.49 h60
M5 Assembly Top:
  lines w10: -292,-930.17 6308,-930.17 ; -292,-726.83 6310,-726.83 ; -292,-523.5 -292,-1133.5 3713,-1133.5 6310,-1133.5 6310,-523.5 -291.5,-523.5 -291.5,-1133.5 1284,-1133.5 ; 2173,-1133.5 2173,-523.5 ; 3440,-726.83 3440,-523.5 ; 4280,-726.83 4280,-523.5 ; 4902,-1140 4902,-937.17
  text "COMPONENTS MARKED 'DNP' SHOULD NOT BE POPULATED." at 1153.5,-318.5 h60
  text "ASSEMBLY VARIANT:" at 1153,-434 h60
  text ".VariantName" at 2189,-434 h60
  text "PCB VIEWED FROM TOP SIDE" at -228.5,-655.67 h60
  text "BOARD #:" at 2248,-655.67 h60
  text ".PRJ_Number" at 2793.5,-655.67 h60
  text "REV:" at 3638,-655.67 h60
  text ".PCB_Rev" at 3929.5,-655.67 h60
  text "SVN REV:" at 4476,-655.67 h60
  text ".VersionControl_RevNumber" at 4982,-655.67 h60
  text "PLOT NAME =" at -228.5,-1064.34 h60
  text ".plot_File_Name" at 577,-1064.34 h60
  text "GENERATED    :" at 2250,-1064.34 h60
  text ".Print_Date" at 3119.5,-1064.34 h60
  text ".Print_Time" at 3848.5,-1064.34 h60
  text "TEXAS INSTRUMENTS" at 5113,-1064.34 h60
M6 Assembly Bottom:
  lines w10: -292.5,-727.33 6309.5,-727.33 ; -290.5,-930.67 6309.5,-930.67 ; 1115.5,-1140.5 1115.5,-937.67 ; 1737.5,-727.33 1737.5,-524 ; 2577.5,-727.33 2577.5,-524 ; 3844.5,-1134 3844.5,-524 ; 4733.5,-1134 6309,-1134 6309,-524 -292.5,-524 -292.5,-1134 2304.5,-1134 6309.5,-1134 6309.5,-524
  text "COMPONENTS MARKED 'DNP' SHOULD NOT BE POPULATED." at 6102,-318 h60
  text ".VariantName" at 5058,-434 h60
  text "ASSEMBLY VARIANT:" at 6097,-434 h60
  text ".VersionControl_RevNumber" at 1035.5,-656.17 h60
  text "SVN REV:" at 1541.5,-656.17 h60
  text ".PCB_Rev" at 2088,-656.17 h60
  text "REV:" at 2379.5,-656.17 h60
  text ".PRJ_Number" at 3224,-656.17 h60
  text "BOARD #:" at 3769.5,-656.17 h60
  text "PCB VIEWED FROM BOTTOM SIDE" at 6246,-656.17 h60
  text "TEXAS INSTRUMENTS" at 904.5,-1064.84 h60
  text ".Print_Time" at 2169,-1064.84 h60
  text ".Print_Date" at 2898,-1064.84 h60
  text "GENERATED    :" at 3767.5,-1064.84 h60
  text ".plot_File_Name" at 5440.5,-1064.84 h60
  text "PLOT NAME =" at 6246,-1064.84 h60
M9 Title Sheet:
  drawing of 56 lines, arcs and shapes, not listed
  text "1" at 1058.34,13381.39 h70
  text "2" at 4384,13381.39 h70
  text "3" at 7714,13381.39 h70
  text "4" at 11049,13381.39 h70
  text "5" at 14374,13381.39 h70
  text "6" at 17709,13381.39 h70
  text "A" at -463,11603.39 h70
  text "A" at 19237,11603.39 h70
  text "B" at -463,7853.39 h70
  text "B" at 19237,7853.39 h70
  text "C" at -463,4103.39 h70
  text "C" at 19237,4103.39 h70
  text "D" at -463,353.39 h70
  text "D" at 19237,353.39 h70
  text "PROJECT TITLE:" at 16143,268.39 h45
  text ".PRJ_Title" at 16193,135.06 h70
  text "DESIGNED FOR:" at 16143,-32.61 h45
  text ".PRJ_Customer" at 16193,-172.61 h70
  text "FILE NAME:" at 16143,-332.61 h45
  text ".PCB_File_Name_No_Path" at 16193,-452.61 h70
  text "Texas Instruments (TI) and/or its licensors do not warrant the accuracy or completeness of this specification" at 11173.5,-614.45 h45
  text "ENGINEER:" at 16143,-622.61 h45
  text "LAYOUT BY:" at 17648,-622.61 h45
  text "or any information contained therein. TI and/or its licensors do not warrant that this design will meet" at 11128.51,-727.11 h45
  text ".PRJ_Engineer" at 16193,-777.6 h70
  text ".PCB_Layout" at 17698.5,-777.6 h70
  text "the specifications, will be suitable for your application or fit for any particular purpose, or will operate in" at 11128.51,-839.78 h45
  text ".Layer_Name" at 577,-858.49 h60
  text "ALTIUM DESIGNER VERSION:" at 17648,-932.61 h45
  text "an implementation. TI and/or its licensors do not warrant that the design is production worthy. You should" at 11128.51,-952.44 h45
  text "completely validate and test your design implementation to confirm the system functionality for your application." at 11173.5,-1065.11 h45
  text ".print_Scale" at 16193,-1065.94 h70
  text ".Application_BuildNumber" at 17698.5,-1065.94 h70
  text "1" at 1058.34,-1318.61 h70
  text "2" at 4384,-1318.61 h70
  text "3" at 7714,-1318.61 h70
  text "4" at 11049,-1318.61 h70
  text "5" at 14374,-1318.61 h70
  text "6" at 17709,-1318.61 h70
M10 Fab Notes:
  drawing of 213 lines, arcs and shapes, not listed
  text "M10 Fab Notes" at 16103.19,9538.99 h60
  text "DESIGN INFORMATION" at 17181.52,9421.87 h60
  text "MIN. TRACK WIDTH:" at 16536.96,9289.74 h60
  text "5" at 17633.2,9289.74 h60
  text "MIL" at 17787.96,9289.74 h60
  text "MIN. CLEARANCE:" at 16536.96,9165.62 h60
  text "MIL" at 17787.96,9165.62 h60
  text "5" at 17633.42,9163.98 h60
  text "MIN. VIA PAD SIZE:" at 16536.96,9041.49 h60
  text "18" at 17603.21,9041.49 h60
  text "MIL" at 17787.96,9041.49 h60
  text "0.05mm (2MIL)" at 17231.96,8911.59 h60
  text "MINIMUM ANNULAR RING" at 16207.73,8903.37 h60
  text "EXTERNAL" at 17939.96,8903.37 h60
  text "PER" at 16407.73,8793.24 h60
  text "IPC-D-275 CLASS 2 LEVEL C" at 16627.73,8793.24 h60
  text "MIL, HOLES" at 18115.96,8692.76 h60
  text "+/-" at 17723.5,8684.18 h60
  text "+/-" at 18577.5,8684.18 h60
  text "REGISTRATION TOLERANCES:" at 16207.73,8683.11 h60
  text "METAL" at 17407.5,8683.11 h60
  text "5" at 17983.7,8683.12 h60
  text "3" at 18816.7,8683.12 h60
  text "MIL" at 18932.96,8683.11 h60
  text "HOLE SIZE TOLERANCE (UNLESS OTHERWISE SPECIFIED):" at 16207.73,8584.8 h60
  text "+/-" at 18577.5,8581.92 h60
  text "3" at 18816.7,8580.86 h60
  text "MIL" at 18932.96,8580.86 h60
  text "MATERIAL:" at 16132.96,8443.21 h60
  text "UNIFORM STACKUP" at 17867.01,8348.29 h60
  text "HYBRID STACKUP" at 16841.48,8341.02 h60
  text "X" at 17725,8340 h60
  text "ISOLA FR408HR" at 16547.68,8177.37 h60
  text "X" at 16403.5,8170.36 h60
  text "Megtron 4    Isola I-Speed" at 16538.93,7976.12 h60
  text "OR" at 16988.92,7976.12 h60
  text "Megtron6    Isola MT-40    Nelco MW-1000" at 16538.93,7779.27 h60
  text "OR" at 16940.28,7779.27 h60
  text "OR" at 17639.01,7779.27 h60
  text "OTHER" at 16578.93,7582.42 h60
  text "X" at 16756.39,7385.94 h60
  text "62 MIL (1.6mm) +/-10%" at 16877.21,7384.84 h60
  text "92 MIL  +/-10%" at 18453.18,7384.84 h60
  text "THICKNESS:" at 16210.88,7376.62 h60
  text "OTHER" at 18162.11,7376.62 h60
  text "TOLERANCE:" at 16210.88,7238.3 h60
  text "X" at 17059.11,7238.3 h60
  text "ANSI IPC-6012 TYPE 3 CLASS 2" at 17237.12,7238.3 h60
  text "OTHER +/-" at 17237.11,7094.11 h60
  text "BOW & TWIST:" at 16210.88,6948.92 h60
  text "X" at 17059.11,6948.92 h60
  text "ANSI IPC-6012 TYPE 3 CLASS 2" at 17237.12,6948.92 h60
  text "OTHER +/-" at 17237.11,6802.23 h60
  text "DRILLING:" at 16136.11,6671.61 h60
  text "NC_DRILL FILES" at 17897.11,6566.42 h60
  text "REFERENCE:" at 16210.88,6562.48 h60
  text "X" at 16868.11,6562.39 h60
  text "AS SHOWN" at 17046.11,6562.48 h60
  text "X" at 17769.11,6562.48 h60
  text "OTHER" at 18195.11,6420.23 h60
  text "PTH COPPER THICKNESS:" at 16210.55,6416.7 h60
  text "X" at 17349.79,6416.7 h60
  text "20-30 um" at 17477.79,6416.7 h60
  text "BOARD FINISH:" at 16136.11,6269.1 h60
  text "SILKSCREEN:" at 16291.33,6158.98 h60
  text "X" at 17249.11,6158.98 h60
  text "TOP" at 17366.11,6158.98 h60
  text "X" at 17759.11,6158.98 h60
  text "BOTTOM" at 17877.11,6158.98 h60
  text "SILKSCREEN COLOR:" at 16291.33,6003.79 h60
  text "X" at 17249.11,6003.79 h60
  text "WHITE" at 17366.11,6003.79 h60
  text "OTHER" at 17877.11,6003.79 h60
  text "RED" at 18482.9,5866.47 h60
  text "X" at 17971.79,5863.76 h60
  text "GREEN" at 17497.11,5860.34 h60
  text "OTHER" at 18115.11,5860.34 h60
  text "SOLDER RESIST COLOR:" at 16291.33,5853.47 h60
  text "X" at 17379.11,5706.09 h60
  text "MATTE" at 17497.11,5706.09 h60
  text "SEMI-GLOSS" at 18114.65,5705.45 h60
  text "X" at 17009.34,5533.32 h60
  text "IMMERSION GOLD (ENIG)" at 17197.11,5533.32 h60
  text "ENEPIG" at 18534.65,5526.1 h60
  text "SURFACE FINISH:" at 16136.11,5525.1 h60
  text "IMM. TIN/SILVER OR EQUIV" at 16465.65,5387.78 h60
  text "HARD GOLD (30u)" at 17897.11,5383.84 h60
  text "OTHER" at 16490.65,5186.99 h60
  text "ARRAY/PANEL:" at 16136.11,5031.62 h60
  text "CUT AND TRIM PER M1 BOARD OUTLINE" at 17197.11,5023.39 h60
  text "N.C. ROUTE" at 17197.11,4887.43 h60
  text "X" at 17885.11,4887.43 h60
  text "V. SCORE" at 18063.11,4887.43 h60
  text "CERTIFICATION:" at 16136.11,4758.3 h60
  text "MATERIALS AND WORKMANSHIP FOR ALL PCBS" at 16861.11,4758.3 h60
  text "TO MEET OR EXCEED THE REQUIREMENTS OF:" at 16861.11,4664.24 h60
  text "X" at 16498.62,4535.61 h60
  text "ANSI IPC-A-600F CLASS ->" at 16626.61,4535.61 h60
  text "X" at 18274.62,4535.61 h60
  text "2" at 18384.61,4535.61 h60
  text "1" at 18069.61,4534.11 h60
  text "3" at 18738.61,4534.11 h60
  text "X" at 17310.62,4387.92 h60
  text "RoHS" at 17438.61,4387.92 h60
  text "OTHER" at 18083.01,4387.92 h60
  text "PER ORDER" at 18480.07,4387.92 h60
  text "ALL BOARDS MUST MEET OR EXCEED UL94-V0 REQUIREMENTS." at 16163.65,4234.1 h60
  text "PCB MUST BEAR THE UL94V-0 UL REGISTERED MATERIAL ID NUMBER" at 16163.65,4118.03 h60
  text "ADDITIONAL REQUIREMENTS:" at 16136.11,3948.61 h60
  text "MICROSECTION:" at 16210.88,3841.48 h60
  text "YES" at 17116.61,3841.48 h60
  text "REQUIRED" at 17978.11,3697.15 h60
  text "BARE BOARD ELEC. TEST:" at 16210.88,3694.29 h60
  text "NONE" at 17516.61,3694.29 h60
  text "X" at 17860.11,3694.29 h60
  text "PER ORDER" at 18570.11,3694.29 h60
  text "FAB INSTRUCTIONS" at 16207.95,3403.28 h100
  text "X" at 16255.41,3252.08 h60
  text "16 MIL & SMALLER VIAS REQUIRE NON-CONDUCTIVE FILL AND PLANARIZE" at 16362.95,3163.28 h59
  text "X" at 16250.41,3057.08 h60
  text "OUTTER LAYER TRACKS 9.7 MIL WIDE REQUIRE 50 OHM SINGLE-ENDED IMPEDANCE" at 16365.9,2952.65 h60
  text "X" at 16255.41,2847.08 h60
  text "OUTTER LAYER TRACKS 5.2 MIL WIDE WITH 4 MIL AIR GAP REQUIRE 100 OHM DIFFERENTIAL IMPEDANCE" at 16365.9,2747.93 h60
  text "INNER LAYER XX & XX TRACKS XX MIL WIDE REQUIRE 50 OHM SINGLE-ENDED IMPEDANCE" at 16365.9,2543.21 h60
  text "INNER LAYER TRACKS XX MIL WIDE WITH   / XX MIL SPACE REQUIRE 100 OHM DIFFERENTIAL IMPEDANCE" at 16360,2349.31 h60
  text "NO PULL-BACK ON COPPER FEATURES TO EDGE OF THE BOARD" at 16357.04,2144.58 h60
  text ".Layer_Name" at 577,-858.49 h60
M11 Gerber Information:
  lines w10: -292,-930.17 6308,-930.17 ; -292,-726.83 6310,-726.83 ; -292,-523.5 -292,-1133.5 3713,-1133.5 6310,-1133.5 6310,-523.5 -291.5,-523.5 -291.5,-1133.5 1284,-1133.5 ; 2173,-1133.5 2173,-523.5 ; 3440,-726.83 3440,-523.5 ; 4280,-726.83 4280,-523.5 ; 4902,-1140 4902,-937.17
  text "ALL ARTWORK VIEWED FROM TOP SIDE" at -228.5,-655.67 h60
  text "BOARD #:" at 2248,-655.67 h60
  text ".PRJ_Number" at 2793.5,-655.67 h60
  text "REV:" at 3638,-655.67 h60
  text ".PCB_Rev" at 3929.5,-655.67 h60
  text "SVN REV:" at 4476,-655.67 h60
  text ".VersionControl_RevNumber" at 4982,-655.67 h60
  text "LAYER NAME =" at -228.5,-858.49 h60
  text "PLOT NAME =" at -228.5,-1064.34 h60
  text ".plot_File_Name" at 577,-1064.34 h60
  text "GENERATED    :" at 2250,-1064.34 h60
  text ".Print_Date" at 3119.5,-1064.34 h60
  text ".Print_Time" at 3848.5,-1064.34 h60
  text "TEXAS INSTRUMENTS" at 5113,-1064.34 h60
M12 Stackup:
  drawing of 607 lines, arcs and shapes, not listed
  text "Layer" at 9956.79,4031.7 h60
  text "Name" at 10366.7,4031.7 h60
  text "Material" at 11296.44,4031.7 h60
  text "Thickness" at 12156.21,4031.7 h60
  text "Constant" at 12806.04,4031.7 h60
  text "Board Layer Stack" at 13375.91,4031.7 h60
  text "Top Overlay" at 10366.7,3911.7 h60
  text "Top Solder" at 10366.7,3791.7 h60
  text "Solder Resist" at 11296.44,3791.7 h60
  text "0.40mil" at 12156.21,3791.7 h60
  text "3.5" at 12806.04,3791.7 h60
  text "1" at 9956.79,3671.7 h60
  text "Top Layer" at 10366.7,3671.7 h60
  text "1.40mil" at 12156.21,3671.7 h60
  text "Dielectric 1" at 10366.7,3551.7 h60
  text "FR408HR" at 11296.44,3551.7 h60
  text "5.00mil" at 12156.21,3551.7 h60
  text "3.62" at 12806.04,3551.7 h60
  text "2" at 9956.79,3431.7 h60
  text "L2 GND" at 10366.7,3431.7 h60
  text "CF-004" at 11296.44,3431.7 h60
  text "1.40mil" at 12156.21,3431.7 h60
  text "Dielectric 3" at 10366.7,3311.7 h60
  text "FR408HR" at 11296.44,3311.7 h60
  text "3.20mil" at 12156.21,3311.7 h60
  text "3.46" at 12806.04,3311.7 h60
  text "3" at 9956.79,3191.7 h60
  text "L3 PWR" at 10366.7,3191.7 h60
  text "CF-004" at 11296.44,3191.7 h60
  text "1.40mil" at 12156.21,3191.7 h60
  text "Dielectric 5" at 10366.7,3071.7 h60
  text "FR408HR" at 11296.44,3071.7 h60
  text "3.00mil" at 12156.21,3071.7 h60
  text "3.6" at 12806.04,3071.7 h60
  text "4" at 9956.79,2951.7 h60
  text "L4 GND" at 10366.7,2951.7 h60
  text "CF-004" at 11296.44,2951.7 h60
  text "1.40mil" at 12156.21,2951.7 h60
  text "Dielectric 7" at 10366.7,2831.7 h60
  text "FR408HR" at 11296.44,2831.7 h60
  text "9.20mil" at 12156.21,2831.7 h60
  text "3.68" at 12806.04,2831.7 h60
  text "5" at 9956.79,2711.7 h60
  text "L5 SIG" at 10366.7,2711.7 h60
  text "CF-004" at 11296.44,2711.7 h60
  text "1.40mil" at 12156.21,2711.7 h60
  text "Dielectric1" at 10366.7,2591.7 h60
  text "FR408HR" at 11296.44,2591.7 h60
  text "6.40mil" at 12156.21,2591.7 h60
  text "3.46" at 12806.04,2591.7 h60
  text "6" at 9956.79,2471.7 h60
  text "L6 GND" at 10366.7,2471.7 h60
  text "CF-004" at 11296.44,2471.7 h60
  text "1.40mil" at 12156.21,2471.7 h60
  text "Dielectric 8" at 10366.7,2351.7 h60
  text "FR408HR" at 11296.44,2351.7 h60
  text "9.20mil" at 12156.21,2351.7 h60
  text "3.68" at 12806.04,2351.7 h60
  text "7" at 9956.79,2231.7 h60
  text "L7 GND" at 10366.7,2231.7 h60
  text "CF-004" at 11296.44,2231.7 h60
  text "1.40mil" at 12156.21,2231.7 h60
  text "Dielectric 6" at 10366.7,2111.7 h60
  text "FR408HR" at 11296.44,2111.7 h60
  text "3.00mil" at 12156.21,2111.7 h60
  text "3.6" at 12806.04,2111.7 h60
  text "8" at 9956.79,1991.7 h60
  text "L8 PWR" at 10366.7,1991.7 h60
  text "CF-004" at 11296.44,1991.7 h60
  text "1.40mil" at 12156.21,1991.7 h60
  text "Dielectric 4" at 10366.7,1871.7 h60
  text "FR408HR" at 11296.44,1871.7 h60
  text "3.20mil" at 12156.21,1871.7 h60
  text "3.46" at 12806.04,1871.7 h60
  text "9" at 9956.79,1751.7 h60
  text "L9 GND" at 10366.7,1751.7 h60
  text "CF-004" at 11296.44,1751.7 h60
  text "1.40mil" at 12156.21,1751.7 h60
  text "Dielectric 2" at 10366.7,1631.7 h60
  text "FR408HR" at 11296.44,1631.7 h60
  text "5.00mil" at 12156.21,1631.7 h60
  text "3.62" at 12806.04,1631.7 h60
  text "10" at 9956.79,1511.7 h60
  text "Bottom Layer" at 10366.7,1511.7 h60
  text "1.40mil" at 12156.21,1511.7 h60
  text "Bottom Solder" at 10366.7,1391.7 h60
  text "Solder Resist" at 11296.44,1391.7 h60
  text "0.40mil" at 12156.21,1391.7 h60
  text "3.5" at 12806.04,1391.7 h60
  text "Bottom Overlay" at 10366.7,1271.7 h60
  text "Total board thickness:" at 9956.79,1151.7 h60
  text "62.00mil" at 12156.21,1151.7 h60
  text ".Layer_Name" at 577,-858.49 h60
Drill Drawing:
  drawing of 165 lines, arcs and shapes, not listed
  text "Symbol" at 101.6,5120 h48
  text "Count" at 449.52,5120 h48
  text "Hole Size" at 889.4,5120 h48
  text "Plated" at 1662.51,5120 h48
  text "Hole Type" at 2010.43,5120 h48
  text "Drill Layer Pair" at 2510.3,5120 h48
  text "Via/Pad" at 3516.66,5120 h48
  text "Pad Shape" at 3920.56,5120 h48
  text "Template" at 4653.69,5120 h48
  text "Description" at 5806.67,5120 h48
  text "Hole Tolerance (+)" at 6386.52,5120 h48
  text "Hole Tolerance (-)" at 7286.26,5120 h48
  text "1" at 449.52,5020 h40
  text "39.76mil (1.010mm)" at 889.4,5020 h40
  text "PTH" at 1662.51,5020 h40
  text "Slot" at 2010.43,5020 h40
  text "Top Layer - Bottom Layer" at 2510.3,5020 h40
  text "Pad" at 3516.66,5020 h40
  text "Rounded" at 3920.56,5020 h40
  text "r430_170h101_356r85" at 4653.69,5020 h40
  text "2" at 449.52,4920 h40
  text "25.59mil (0.650mm)" at 889.4,4920 h40
  text "NPTH" at 1662.51,4920 h40
  text "Round" at 2010.43,4920 h40
  text "Top Layer - Bottom Layer" at 2510.3,4920 h40
  text "Pad" at 3516.66,4920 h40
  text "Rounded" at 3920.56,4920 h40
  text "c65hn65m65p0" at 4653.69,4920 h40
  text "A" at 79.91,4910.01 h44.44
  text "2" at 449.52,4820 h40
  text "29.92mil (0.760mm)" at 889.4,4820 h40
  text "PTH" at 1662.51,4820 h40
  text "Slot" at 2010.43,4820 h40
  text "Top Layer - Bottom Layer" at 2510.3,4820 h40
  text "Pad" at 3516.66,4820 h40
  text "Rounded" at 3920.56,4820 h40
  text "r380_150h76_305r75" at 4653.69,4820 h40
  text "2" at 449.52,4720 h40
  text "50.00mil (1.270mm)" at 889.4,4720 h40
  text "NPTH" at 1662.51,4720 h40
  text "Round" at 2010.43,4720 h40
  text "Top Layer - Bottom Layer" at 2510.3,4720 h40
  text "Pad" at 3516.66,4720 h40
  text "Rounded" at 3920.56,4720 h40
  text "c127hn127" at 4653.69,4720 h40
  text "2" at 449.52,4620 h40
  text "55.12mil (1.400mm)" at 889.4,4620 h40
  text "PTH" at 1662.51,4620 h40
  text "Slot" at 2010.43,4620 h40
  text "Top Layer - Bottom Layer" at 2510.3,4620 h40
  text "Pad" at 3516.66,4620 h40
  text "Rounded Rectangle" at 3920.56,4620 h40
  text "r100_180h140_60r50m100_180p0" at 4653.69,4620 h40
  text "C" at 79.91,4610.01 h44.44
  text "2" at 449.52,4520 h40
  text "63.00mil (1.600mm)" at 889.4,4520 h40
  text "PTH" at 1662.51,4520 h40
  text "Round" at 2010.43,4520 h40
  text "Top Layer - Bottom Layer" at 2510.3,4520 h40
  text "Pad" at 3516.66,4520 h40
  text "Rounded" at 3920.56,4520 h40
  text "c221h160" at 4653.69,4520 h40
  text "2" at 449.52,4420 h40
  text "66.93mil (1.700mm)" at 889.4,4420 h40
  text "PTH" at 1662.51,4420 h40
  text "Slot" at 2010.43,4420 h40
  text "Top Layer - Bottom Layer" at 2510.3,4420 h40
  text "Pad" at 3516.66,4420 h40
  text "Rounded Rectangle" at 3920.56,4420 h40
  text "r100_210h170_60r50m100_210p0" at 4653.69,4420 h40
  text "B" at 79.91,4410.01 h44.44
  text "2" at 449.52,4320 h40
  text "105.91mil (2.690mm)" at 889.4,4320 h40
  text "NPTH" at 1662.51,4320 h40
  text "Round" at 2010.43,4320 h40
  text "Top Layer - Bottom Layer" at 2510.3,4320 h40
  text "Pad" at 3516.66,4320 h40
  text "Rounded" at 3920.56,4320 h40
  text "c-127hn269" at 4653.69,4320 h40
  text "2" at 449.52,4220 h40
  text "133.86mil (3.400mm)" at 889.4,4220 h40
  text "PTH" at 1662.51,4220 h40
  text "Round" at 2010.43,4220 h40
  text "Top Layer - Bottom Layer" at 2510.3,4220 h40
  text "Pad" at 3516.66,4220 h40
  text "Rounded" at 3920.56,4220 h40
  text "c550h340m550p0" at 4653.69,4220 h40
  text "3" at 449.52,4120 h40
  text "42.91mil (1.090mm)" at 889.4,4120 h40
  text "PTH" at 1662.51,4120 h40
  text "Round" at 2010.43,4120 h40
  text "Top Layer - Bottom Layer" at 2510.3,4120 h40
  text "Pad" at 3516.66,4120 h40
  text "(Mixed)" at 3920.56,4120 h40
  text "(Mixed)" at 4653.69,4120 h40
  text "6" at 449.52,4020 h40
  text "47.24mil (1.200mm)" at 889.4,4020 h40
  text "PTH" at 1662.51,4020 h40
  text "Round" at 2010.43,4020 h40
  text "Top Layer - Bottom Layer" at 2510.3,4020 h40
  text "Pad" at 3516.66,4020 h40
  text "(Mixed)" at 3920.56,4020 h40
  text "(Mixed)" at 4653.69,4020 h40
  text "10" at 449.52,3920 h40
  text "40.00mil (1.016mm)" at 889.4,3920 h40
  text "PTH" at 1662.51,3920 h40
  text "Round" at 2010.43,3920 h40
  text "Top Layer - Bottom Layer" at 2510.3,3920 h40
  text "Pad" at 3516.66,3920 h40
  text "(Mixed)" at 3920.56,3920 h40
  text "(Mixed)" at 4653.69,3920 h40
  text "12" at 449.52,3820 h40
  text "28.00mil (0.711mm)" at 889.4,3820 h40
  text "PTH" at 1662.51,3820 h40
  text "Round" at 2010.43,3820 h40
  text "Top Layer - Bottom Layer" at 2510.3,3820 h40
  text "Pad" at 3516.66,3820 h40
  text "(Mixed)" at 3920.56,3820 h40
  text "(Mixed)" at 4653.69,3820 h40
  text "14" at 449.52,3720 h40
  text "20.00mil (0.508mm)" at 889.4,3720 h40
  text "PTH" at 1662.51,3720 h40
  text "Round" at 2010.43,3720 h40
  text "Top Layer - Bottom Layer" at 2510.3,3720 h40
  text "Via" at 3516.66,3720 h40
  text "Rounded" at 3920.56,3720 h40
  text "v102h51m0mx0" at 4653.69,3720 h40
  text "32" at 449.52,3620 h40
  text "66.93mil (1.700mm)" at 889.4,3620 h40
  text "PTH" at 1662.51,3620 h40
  text "Round" at 2010.43,3620 h40
  text "Top Layer - Bottom Layer" at 2510.3,3620 h40
  text "Pad" at 3516.66,3620 h40
  text "Rounded" at 3920.56,3620 h40
  text "c260h170m260p0" at 4653.69,3620 h40
  text "43" at 449.52,3520 h40
  text "7.87mil (0.200mm)" at 889.4,3520 h40
  text "PTH" at 1662.51,3520 h40
  text "Round" at 2010.43,3520 h40
  text "Top Layer - Bottom Layer" at 2510.3,3520 h40
  text "Pad" at 3516.66,3520 h40
  text "Rounded" at 3920.56,3520 h40
  text "(Mixed)" at 4653.69,3520 h40
  text "958" at 449.52,3420 h40
  text "8.00mil (0.203mm)" at 889.4,3420 h40
  text "PTH" at 1662.51,3420 h40
  text "Round" at 2010.43,3420 h40
  text "Top Layer - Bottom Layer" at 2510.3,3420 h40
  text "(Mixed)" at 3516.66,3420 h40
  text "Rounded" at 3920.56,3420 h40
  text "(Mixed)" at 4653.69,3420 h40
  text "1095 Total" at 449.52,3320 h40
  text "Slot definitions :" at 101.6,3216.68 h40
  text "Routed Path Length" at 799.39,3216.68 h40
  text "= Calculated from tool start centre position to tool end centre position." at 1543.84,3216.68 h40
  text "Hole Length" at 799.39,3143.37 h40
  text "= Routed Path Length + Tool Size = Slot length as defined in the PCB layout" at 1270.59,3143.37 h40
  text ".Layer_Name" at 577,-858.49 h60

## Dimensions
0,100 to 3900,100 on M2 Board Dimensions
100,2716.54 to 100,0 on M2 Board Dimensions
0,-400 to 1000,-400 on M2 Board Dimensions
